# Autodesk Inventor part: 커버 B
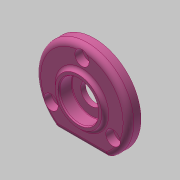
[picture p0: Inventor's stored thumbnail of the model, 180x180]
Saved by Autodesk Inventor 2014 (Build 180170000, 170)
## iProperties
Created: 2020-04
Part Number: 커버 B
Material: 알루미늄 6061
Document SubType Name: Modeling
Designer: mduedu
Density: 2.71 g/cm^3
Appearance: Pink
Mass: 33.6775 g
Surface Area: 62.2844 cm^2
Volume: 12.4271 cm^3
Author: mduedu
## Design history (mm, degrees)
sketch "스케치1"
  geometry: C1 r 26 at (0, 0); 1 further point
  constraints: 1 centre point, 1 coincident
  dimensions: "d0" = 52 diameter of C1
extrude "돌출1" new body sketch "스케치1" distance "d1" = 7; taper "d2" = 0 deg
sketch "스케치2"
  geometry: L1 (-14.62, -21.5)-(14.62, -21.5); A1 r 26 centre (0, 0) between (-14.62, -21.5) and (14.62, -21.5) reference; 1 further point
  constraints: 2 end point, 2 point on circle, 1 horizontal
  dimensions: "d3" = 21.5 distance from line of L1 point (0, 0)
extrude "돌출2" cut sketch "스케치2" stored distance "d4" = 7; taper "d5" = 0 deg
sketch "스케치6"
  geometry: C1 r 13 at (0, 0); 1 further point
  constraints: 1 centre point, 1 coincident
  dimensions: "d29" = 26 diameter of C1
extrude "돌출5" join sketch "스케치6" distance "d30" = 2; taper "d31" = 0 deg
fillet "모깎기1" dims "d6" = 3
fillet "모깎기2" dims "d7" = 3
fillet "모깎기4" dims "d33" = 2
sketch "스케치3" dims "d8" = 40
  geometry: 3 further points
  constraints: 2 vertical alignment, 1 coincident, 2 other
hole "구멍1" sketch "스케치3" at (0, 20) diameter "d9" = 4.5; stored, may be unused: countersink angle "d13" = 90 deg, drill point angle "d15" = 118 deg; dims "d10" = 6, "d11" = 8, "d12" = 4.4, "d14" = 8
sketch "스케치4"
  geometry: C1 r 14 at (0, 0); 1 further point
  constraints: 1 centre point, 1 coincident
  dimensions: "d19" = 28 diameter of C1
extrude "돌출3" join sketch "스케치4" distance "d20" = 4; taper "d21" = 0 deg
sketch "스케치5"
  geometry: C1 r 12 at (0, 0); 1 further point
  constraints: 1 centre point, 1 coincident
  dimensions: "d22" = 24 diameter of C1
extrude "돌출4" cut sketch "스케치5" distance "d23" = 3; taper "d24" = 0 deg
fillet "모깎기3" dims "d25" = 3
chamfer "모따기1" distance "d26" = 0.5; stored, may be unused: second distance "d27" = 2, angle "d28" = 45 deg
sketch "스케치7"
  geometry: 2 further points
  constraints: 1 coincident
hole "구멍2" sketch "스케치7" at (0, 0) diameter "d34" = 12; stored, may be unused: countersink angle "d38" = 90 deg, drill point angle "d40" = 118 deg; dims "d35" = 6, "d36" = 22, "d37" = 7.3, "d39" = 8
fillet "모깎기5" dims "d41" = 0.3
chamfer "모따기2" distance "d42" = 0.7; stored, may be unused: second distance "d43" = 2, angle "d44" = 30 deg
node "솔리드1"
pattern_circular "원형 패턴1" dims angle "d17" = 360 deg
node "투영된 루프1"
